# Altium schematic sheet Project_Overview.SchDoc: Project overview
size A4; Date: Not used; ApprovedBy: Not used; CheckedBy: Not used; Author: Ph.A; CompanyName: STMicroelectronics; DrawnBy: Not used; Engineer: Not used; Organization: Not used; Address1: Not used; Address2: Not used; Address3: Not used; Address4: Not used; DocumentNumber: Not used; Revision: Not used; SheetNumber: 1; SheetTotal: 6
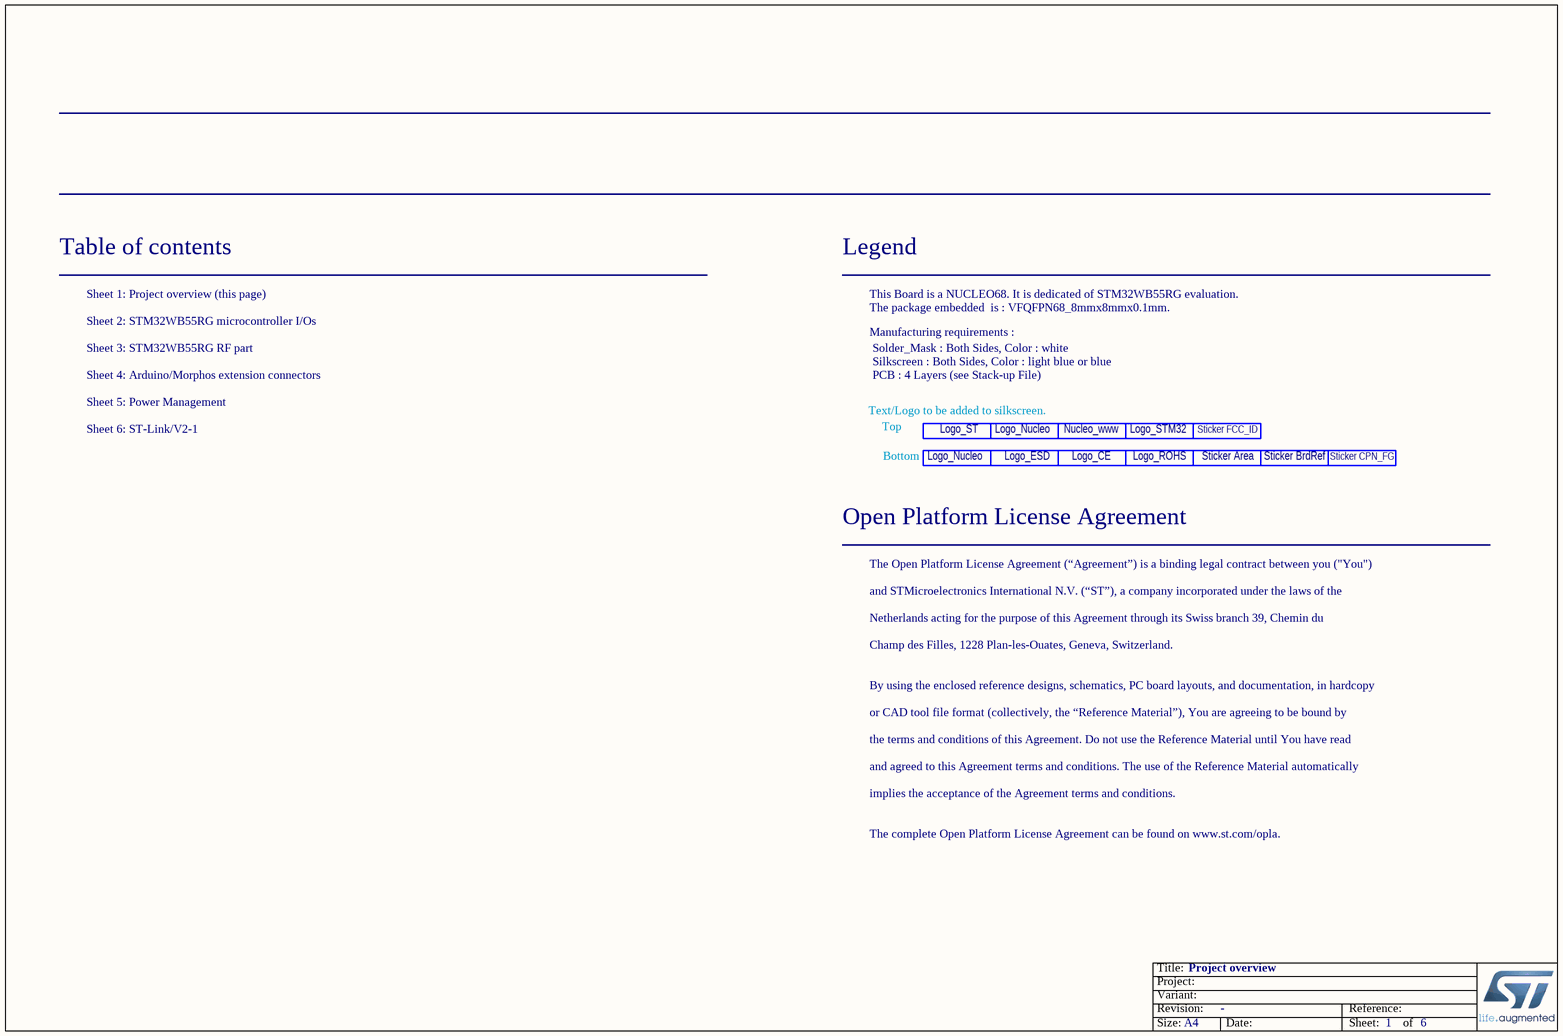
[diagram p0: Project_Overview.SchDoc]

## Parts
Label_1  LOGO_ST  [LOGO_ST_Size3]  (value not drawn)
Label_2  LOGO_ROHS  [SYMBOL_RoHS]  (value not drawn)
Label_3  LOGO_Nucleo_www  [LOGO_Nucleo_www]  (value not drawn)
Label_4  LOGO_STM32  [LOGO_STM32]  (value not drawn)
Label_5  LOGO_Nucleo  [LOGO_Nucleo]  (value not drawn)
Label_6  LOGO_CE  [LOGO CE]  (value not drawn)
Label_7  LOGO_ESD  [LOGO ESD]  (value not drawn)
Label_8  LOGO_StickerArea_W21x6  [LOGO_StickerArea_Border]  (value not drawn)
Label_9  LOGO_Nucleo  [LOGO_Nucleo]  (value not drawn)
STICKER_1  FCC_ID_Sticker_16x5  [Sticker_FCC_ID 16x5mm]  (value not drawn)
STICKER_2  Sticker_BrdRef_21x5  [Sticker_BrdRef_21x5mm]  (value not drawn)
STICKER_3  Sticker_CPN_FG 16x5  [Sticker_CPN_FG 16x5mm]  (value not drawn)

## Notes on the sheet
- Table of contents
- Sheet 1: Project overview (this page)
- Legend
- This Board is a NUCLEO68. It is dedicated of STM32WB55RG evaluation.
- The package embedded  is : VFQFPN68_8mmx8mmx0.1mm.
- Sheet 2: STM32WB55RG microcontroller I/Os
- Sheet 3: STM32WB55RG RF part
- Sheet 4: Arduino/Morphos extension connectors
- Manufacturing requirements :
- Silkscreen : Both Sides, Color : light blue or blue
- Solder_Mask : Both Sides, Color : white
- PCB : 4 Layers (see Stack-up File)
- Sheet 6: ST-Link/V2-1
- Sheet 5: Power Management
- Text/Logo to be added to silkscreen.
- Top
- Bottom
- Open Platform License Agreement
- The Open Platform License Agreement (“Agreement”) is a binding legal contract between you ("You")
- and STMicroelectronics International N.V. (“ST”), a company incorporated under the laws of the
- Netherlands acting for the purpose of this Agreement through its Swiss branch 39, Chemin du
- Champ des Filles, 1228 Plan-les-Ouates, Geneva, Switzerland.
- By using the enclosed reference designs, schematics, PC board layouts, and documentation, in hardcopy
- or CAD tool file format (collectively, the “Reference Material”), You are agreeing to be bound by
- the terms and conditions of this Agreement. Do not use the Reference Material until You have read
- and agreed to this Agreement terms and conditions. The use of the Reference Material automatically
- implies the acceptance of the Agreement terms and conditions.
- The complete Open Platform License Agreement can be found on www.st.com/opla.

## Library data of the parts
Label_1 = LOGO_ST: Silkscreen Only: YES
Label_2 = LOGO_ROHS: Silkscreen Only: YES
Label_4 = LOGO_STM32: Silkscreen Only: YES
Label_5 Label_9 = LOGO_Nucleo: Silkscreen Only: YES
Label_6 = LOGO_CE: Silkscreen Only: YES
Label_7 = LOGO_ESD: Silkscreen Only: YES
Label_8 = LOGO_StickerArea_W21x6: Silkscreen Only: YES
STICKER_1 = LOGO_Sticker_FCC_ID: Sticker for FCC_ID 16x5mm
STICKER_2 = LOGO_Sticker_BrdRef: Sticker_BrdRef 21x5mm
STICKER_3 = LOGO_Sticker_CPN_FG: Sticker for CPN_FG 16x5mm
